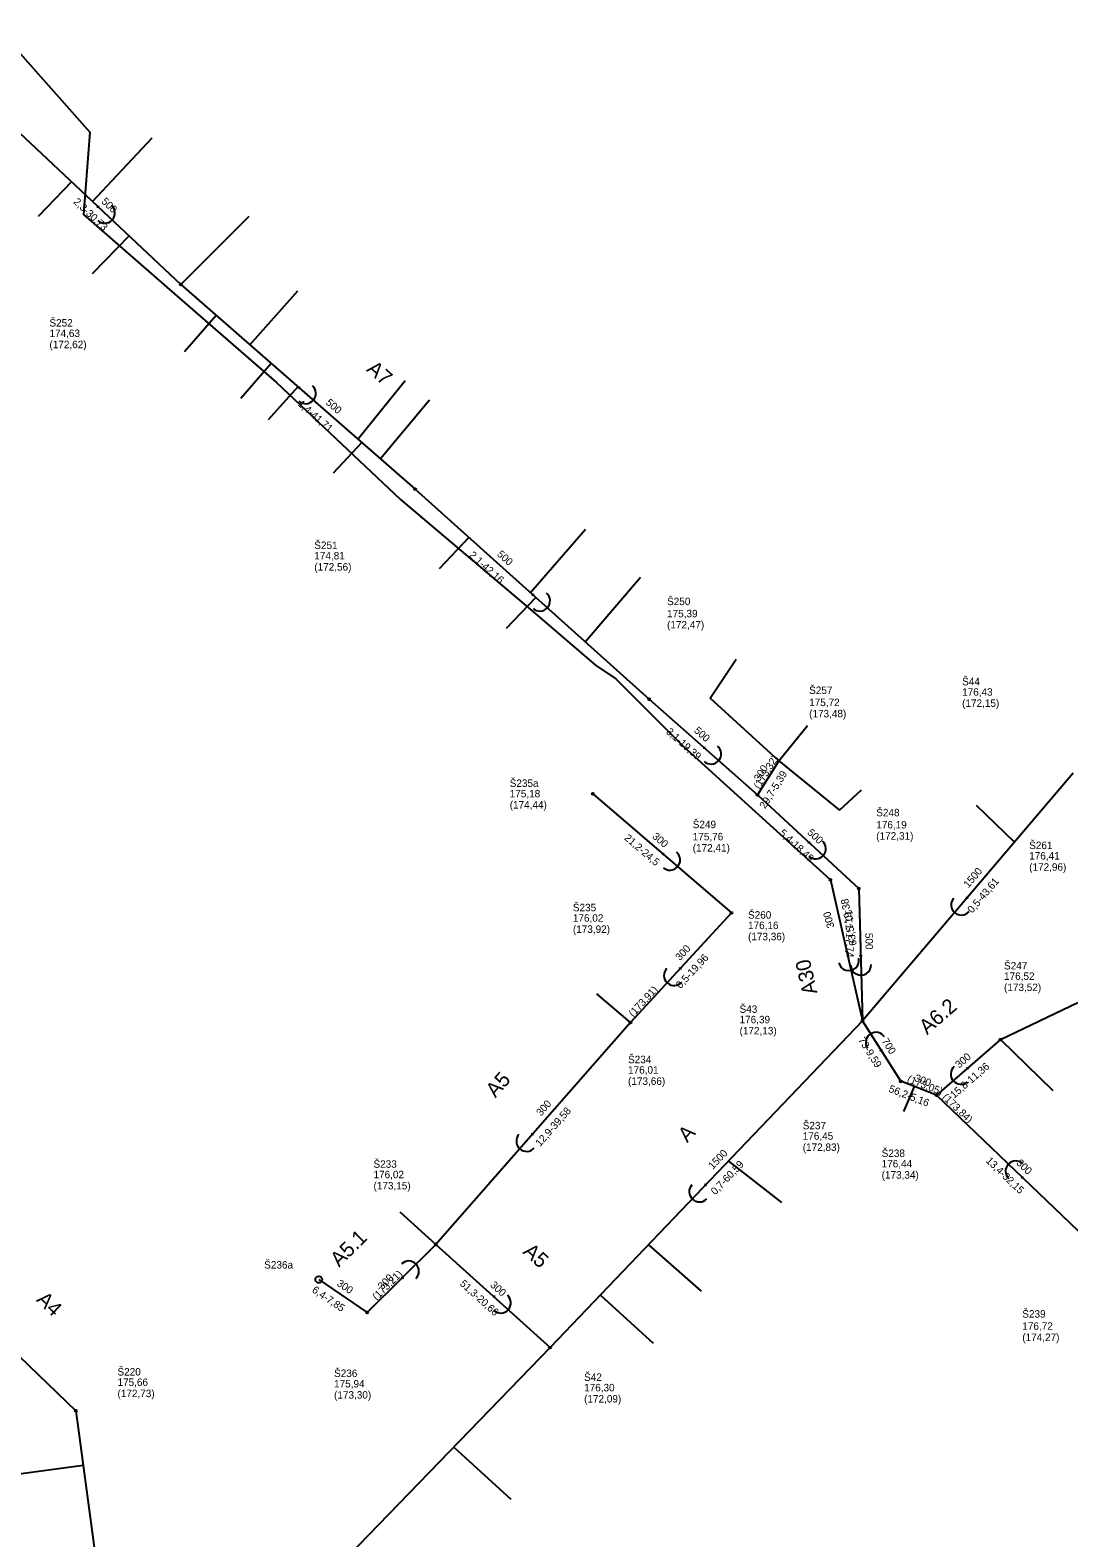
# Model space of a CAD drawing. Extents: x -548529 to -543591, y -1201432 to -1192608.
# Drawn here: x -544467.3 to -544328, y -1193048.7 to -1192846.6 of the extents above; entities that cross this region are included whole.
import ezdxf

# ---------------------------------------------------------------- set-up
doc = ezdxf.new("R2010")
doc.units = 0
for name, color, linetype in [('C3D_Bod-Značky', 7, 'Continuous'), ('C3D_Koridor', 7, 'Continuous'), ('C3D_Křižovatka', 7, 'Continuous'), ('C3D_Netisknutelná', 7, 'Continuous'), ('C3D_PP-zobrazeni v PR', 7, 'Continuous'), ('C3D_PR-Popisek', 7, 'Continuous'), ('C3D_SPR-Popisek', 7, 'Continuous'), ('C3D_Tlakove_potrubi_Popis', 7, 'Continuous'), ('C3D_ZPR-Formaty', 7, 'Continuous')]:
    doc.layers.add(name, color=color, linetype=linetype)

# ---------------------------------------------------------------- blocks, each defined once
blk = doc.blocks.new('100')
at = {"layer": 'Defpoints'}
blk.add_circle((0, 0), 0.127, dxfattribs=at)
blk = doc.blocks.new('101')
at = {"layer": 'Defpoints'}
blk.add_circle((0, 0), 0.463, dxfattribs=at)
blk = doc.blocks.new('86')
at = {"layer": 'Defpoints'}
blk.add_lwpolyline([(0.08, 0.14), (0.19, 0), (0.08, -0.14)], dxfattribs=at)
blk.add_arc((1.37, 0), 1.37, 270, 90, dxfattribs=at)
blk = doc.blocks.new('91')
at = {"layer": 'Defpoints'}
blk.add_lwpolyline([(0.08, 0.14), (0.19, 0), (0.08, -0.14)], dxfattribs=at)
blk.add_arc((1.37, 0), 1.37, 270, 90, dxfattribs=at)

msp = doc.modelspace()

# ---------------------------------------------------------------- linework, layer by layer
at = {"layer": 'C3D_Bod-Značky'}
for points in [[(-544471.435, -1192846.604), (-544459.262, -1192860.285), (-544460.127, -1192871.314), (-544447.171, -1192882.587), (-544434.216, -1192893.86), (-544417.602, -1192909.539), (-544399.58, -1192924.754), (-544391.46, -1192931.747), (-544388.746, -1192933.552), (-544379.638, -1192942.643), (-544359.967, -1192960.53)], [(-544469.46, -1192859.66), (-544447.07, -1192880.71)], [(-544447.07, -1192880.71), (-544415.63, -1192908.12)], [(-544415.63, -1192908.12), (-544384.28, -1192936.31)], [(-544384.28, -1192936.31), (-544369.74, -1192949.14)], [(-544366.86, -1192944.58), (-544369.74, -1192949.14)], [(-544327.39, -1192946.221), (-544355.66, -1192979.427)], [(-544391.799, -1192948.977), (-544373.23, -1192964.96)], [(-544369.74, -1192949.14), (-544356.16, -1192961.69)], [(-544359.967, -1192960.53), (-544355.66, -1192979.427)], [(-544356.16, -1192961.69), (-544355.66, -1192979.427)], [(-544373.23, -1192964.96), (-544386.75, -1192979.65)], [(-544386.75, -1192979.65), (-544412.86, -1193009.39)], [(-544355.66, -1192979.427), (-544397.523, -1193023.229)], [(-544350.53, -1192987.53), (-544355.66, -1192979.427)], [(-544337.14, -1192981.94), (-544345.72, -1192989.39)], [(-544345.72, -1192989.39), (-544350.53, -1192987.53)], [(-544322.5, -1193011.63), (-544345.72, -1192989.39)], [(-544494.08, -1192999.977), (-544461.138, -1193031.699)], [(-544422.07, -1193018.52), (-544412.86, -1193009.39)], [(-544412.86, -1193009.39), (-544397.523, -1193023.229)], [(-544428.557, -1193014.1), (-544422.07, -1193018.52)], [(-544397.523, -1193023.229), (-544454.373, -1193081.919)], [(-544461.138, -1193031.699), (-544454.373, -1193081.919)]]:
    msp.add_lwpolyline(points, dxfattribs=at)
at = {"layer": 'C3D_Koridor'}
for points in [[(-544458.902, -1192869.586), (-544450.905, -1192861.027)], [(-544461.721, -1192866.936), (-544466.181, -1192871.572)], [(-544447.07, -1192880.71), (-544437.895, -1192871.53)], [(-544453.994, -1192874.2), (-544458.928, -1192879.253)], [(-544437.785, -1192888.805), (-544431.359, -1192881.545)], [(-544442.299, -1192884.87), (-544446.55, -1192889.71)], [(-544434.942, -1192891.284), (-544439.012, -1192896.004)], [(-544423.318, -1192901.418), (-544416.994, -1192893.554)], [(-544431.35, -1192894.415), (-544435.346, -1192898.828)], [(-544420.297, -1192904.052), (-544413.709, -1192896.161)], [(-544422.77, -1192901.896), (-544426.618, -1192905.99)], [(-544400.182, -1192921.974), (-544392.805, -1192913.485)], [(-544408.421, -1192914.602), (-544412.403, -1192918.82)], [(-544392.835, -1192928.617), (-544385.415, -1192919.931)], [(-544399.45, -1192922.669), (-544403.425, -1192926.815)], [(-544376.1, -1192936.16), (-544372.6, -1192930.915)], [(-544366.86, -1192944.58), (-544376.1, -1192936.16)], [(-544366.86, -1192944.58), (-544363.049, -1192939.835)], [(-544366.86, -1192944.58), (-544358.74, -1192951.18)], [(-544358.74, -1192951.18), (-544355.805, -1192948.43)], [(-544335.26, -1192955.466), (-544340.377, -1192950.531)], [(-544386.75, -1192979.65), (-544391.256, -1192975.813)], [(-544337.14, -1192981.94), (-544326.769, -1192976.978)], [(-544337.14, -1192981.94), (-544330.121, -1192988.738)], [(-544348.744, -1192988.221), (-544350.169, -1192991.567)], [(-544373.617, -1192998.216), (-544366.499, -1193003.785)], [(-544412.86, -1193009.39), (-544417.626, -1193005.091)], [(-544384.347, -1193009.443), (-544377.293, -1193015.657)], [(-544390.801, -1193016.196), (-544383.712, -1193022.645)], [(-544410.471, -1193036.596), (-544402.796, -1193043.551)], [(-544460.152, -1193039.016), (-544482.684, -1193042.051)]]:
    msp.add_lwpolyline(points, dxfattribs=at)

# ---------------------------------------------------------------- block references
at = {"layer": 'C3D_PP-zobrazeni v PR'}
for name, p, xscale, yscale, rotation in [('100', (-544447.07, -1192880.71), 1.0000000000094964, 1.0000000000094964, 137.9999986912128), ('100', (-544415.63, -1192908.12), 1.0000000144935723, 1.0000000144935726, 139.00000089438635), ('100', (-544384.28, -1192936.31), 1.0000000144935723, 1.0000000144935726, 139.00000089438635), ('100', (-544366.86, -1192944.58), 0.9999999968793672, 0.9999999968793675, -122.00000027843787), ('100', (-544391.799, -1192948.977), 1.0000000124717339, 1.0000000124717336, -40.00000131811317), ('100', (-544369.74, -1192949.14), 1.0000000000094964, 1.0000000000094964, 137.9999986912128), ('100', (-544359.967, -1192960.53), 1.0000000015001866, 1.0000000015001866, 120.99999982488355), ('100', (-544356.16, -1192961.69), 1.000000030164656, 1.000000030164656, 114.99999971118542), ('100', (-544373.23, -1192964.96), 1.0000000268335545, 1.0000000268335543, -86.00000028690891), ('100', (-544386.75, -1192979.65), 1.0000000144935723, 1.0000000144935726, -130.99999910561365), ('100', (-544355.66, -1192979.427), 1.0000000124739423, 1.000000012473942, 112.99999954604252), ('100', (-544337.14, -1192981.94), 1.0000000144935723, 1.0000000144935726, -139.00000089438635), ('100', (-544350.53, -1192987.53), 1.000000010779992, 1.0000000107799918, 141.00000108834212), ('100', (-544345.72, -1192989.39), 1.000000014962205, 1.0000000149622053, 89.0000000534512), ('100', (-544412.86, -1193009.39), 1.0000000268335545, 1.0000000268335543, 93.99999971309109), ('101', (-544428.557, -1193014.1), 0.9999999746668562, 0.999999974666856, 145.99999954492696), ('100', (-544422.07, -1193018.52), 1.0011217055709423, 1.0011217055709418, -173.41739016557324), ('100', (-544397.523, -1193023.229), 1.00000000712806, 1.00000000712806, -133.00000056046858), ('100', (-544461.138, -1193031.699), 0.9999999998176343, 0.9999999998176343, 116.9999993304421)]:
    msp.add_blockref(name, p, dxfattribs=dict(at, xscale=xscale, yscale=yscale, rotation=rotation))
at = {"layer": 'C3D_SPR-Popisek'}
for name, p, xscale, yscale, rotation in [('91', (-544458.265, -1192870.185), 1.00000000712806, 1.00000000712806, -43.0000005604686), ('91', (-544431.35, -1192894.415), 1.0000000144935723, 1.0000000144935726, -40.99999910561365), ('91', (-544399.955, -1192922.215), 1.0000000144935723, 1.0000000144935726, -40.99999910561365), ('91', (-544377.01, -1192942.725), 1.0000000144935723, 1.0000000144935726, -40.99999910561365), ('91', (-544362.95, -1192955.415), 1.0000000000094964, 1.0000000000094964, -42.000001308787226), ('91', (-544382.514, -1192956.968), 1.0000000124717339, 1.0000000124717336, -40.00000131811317), ('91', (-544341.525, -1192962.824), 1.0000000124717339, 1.0000000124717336, -130.0000013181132), ('86', (-544357.813, -1192969.978), 0.9999999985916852, 0.9999999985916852, -76.99999972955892), ('91', (-544355.91, -1192970.558), 1.00000001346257, 1.0000000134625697, -88.00000009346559), ('91', (-544379.99, -1192972.305), 1.0000000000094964, 1.0000000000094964, -132.0000013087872), ('91', (-544353.095, -1192983.478), 0.9999999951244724, 0.9999999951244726, 123.00000127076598), ('91', (-544341.43, -1192985.665), 1.0000000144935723, 1.0000000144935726, -139.00000089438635), ('91', (-544399.805, -1192994.52), 1.0000000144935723, 1.0000000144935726, -130.99999910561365), ('91', (-544334.11, -1193000.51), 1.00000000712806, 1.00000000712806, 136.99999943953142), ('91', (-544376.592, -1193001.328), 1.00000000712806, 1.00000000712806, -133.00000056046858), ('91', (-544417.465, -1193013.955), 0.999999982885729, 0.9999999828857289, 45), ('91', (-544405.192, -1193016.31), 1.0000000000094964, 1.0000000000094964, -42.000001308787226)]:
    msp.add_blockref(name, p, dxfattribs=dict(at, xscale=xscale, yscale=yscale, rotation=rotation))

# ---------------------------------------------------------------- texts
at = {"layer": 'C3D_Křižovatka'}
for s, p in [('Š252', (-544464.67, -1192886.34)), ('Š251', (-544429.16, -1192916.16)), ('Š250', (-544381.86, -1192923.69)), ('Š257', (-544362.81, -1192935.6)), ('Š44', (-544342.3, -1192934.431)), ('Š235a', (-544402.959, -1192948.057)), ('Š248', (-544353.81, -1192952)), ('Š249', (-544378.42, -1192953.59)), ('Š261', (-544333.308, -1192956.394)), ('Š235', (-544394.49, -1192964.73)), ('Š260', (-544371.007, -1192965.72)), ('Š247', (-544336.68, -1192972.53)), ('Š43', (-544372.14, -1192978.347)), ('Š234', (-544387.09, -1192985.1)), ('Š237', (-544363.67, -1192993.96)), ('Š238', (-544353.09, -1192997.67)), ('Š233', (-544421.22, -1192999.12)), ('Š236a', (-544435.877, -1193012.63)), ('Š239', (-544334.23, -1193019.21)), ('Š220', (-544455.548, -1193026.969)), ('Š236', (-544426.51, -1193027.17)), ('Š42', (-544392.983, -1193027.689))]:
    msp.add_text(s, height=1, dxfattribs=at).set_placement(p)
at = {"layer": 'C3D_Netisknutelná'}
for s, rotation, p in [('A7', 318.92, (-544422.27, -1192892.228)), ('A30', 102.81, (-544361.694, -1192975.662)), ('A6.2', 40.97, (-544346.992, -1192981.356)), ('A5', 48.72, (-544404.873, -1192989.838)), ('A', 46.3, (-544379.164, -1192995.827)), ('A5.1', 44.75, (-544425.833, -1193012.526)), ('A5', 317.94, (-544401.303, -1193010.524)), ('A4', 316.08, (-544466.527, -1193016.931))]:
    msp.add_text(s, height=2, rotation=rotation, dxfattribs=at).set_placement(p)
at = {"layer": 'C3D_PR-Popisek'}
for s, rotation, p in [('500', 316.77, (-544457.789, -1192869.679)), ('500', 318.92, (-544427.703, -1192896.661)), ('500', 318.04, (-544404.738, -1192916.979)), ('500', 318.58, (-544378.329, -1192940.634)), ('300', 57.72, (-544369.468, -1192947.4)), ('300', 319.28, (-544383.926, -1192954.826)), ('500', 317.26, (-544363.141, -1192954.282)), ('1500', 49.59, (-544341.457, -1192961.67)), ('300', 105.81, (-544359.4, -1192966.834)), ('500', 271.61, (-544355.292, -1192967.642)), ('300', 47.37, (-544380.142, -1192971.434)), ('700', 302.34, (-544353.126, -1192982.122)), ('300', 40.97, (-544342.703, -1192985.84)), ('300', 338.86, (-544348.775, -1192987.455)), ('300', 48.72, (-544398.76, -1192992.264)), ('1500', 46.3, (-544375.716, -1192999.396)), ('300', 316.23, (-544335.114, -1192998.577)), ('300', 44.75, (-544420.056, -1193015.534)), ('300', 325.73, (-544426.237, -1193014.839)), ('300', 317.94, (-544405.653, -1193014.955))]:
    msp.add_text(s, height=1, rotation=rotation, dxfattribs=at).set_placement(p)
at = {"layer": 'C3D_Tlakove_potrubi_Popis'}
for s, p in [('(172,62)', (-544464.67, -1192889.24)), ('174,63 ', (-544464.67, -1192887.74)), ('174,81 ', (-544429.16, -1192917.56)), ('(172,56)', (-544429.16, -1192919.06)), ('175,39 ', (-544381.86, -1192925.32)), ('(172,47)', (-544381.86, -1192926.82)), ('175,72 ', (-544362.81, -1192937.23)), ('(172,15)', (-544342.3, -1192937.331)), ('176,43 ', (-544342.3, -1192935.831)), ('(173,48)', (-544362.81, -1192938.73)), ('175,18 ', (-544402.959, -1192949.457)), ('(174,44)', (-544402.959, -1192950.957)), ('176,19 ', (-544353.81, -1192953.63)), ('175,76 ', (-544378.42, -1192955.22)), ('(172,31)', (-544353.81, -1192955.13)), ('(172,41)', (-544378.42, -1192956.72)), ('176,41 ', (-544333.308, -1192957.794)), ('(172,96)', (-544333.308, -1192959.294)), ('(173,92)', (-544394.49, -1192967.63)), ('176,02 ', (-544394.49, -1192966.13)), ('176,16 ', (-544371.007, -1192967.12)), ('(173,36)', (-544371.007, -1192968.62)), ('176,52 ', (-544336.68, -1192973.93)), ('(173,52)', (-544336.68, -1192975.43)), ('176,39 ', (-544372.14, -1192979.747)), ('(172,13)', (-544372.14, -1192981.247)), ('(173,66)', (-544387.09, -1192988)), ('176,01 ', (-544387.09, -1192986.5)), ('176,45 ', (-544363.67, -1192995.36)), ('(172,83)', (-544363.67, -1192996.86)), ('176,44 ', (-544353.09, -1192999.07)), ('(173,15)', (-544421.22, -1193002.02)), ('176,02 ', (-544421.22, -1193000.52)), ('(173,34)', (-544353.09, -1193000.57)), ('(174,27)', (-544334.23, -1193022.34)), ('176,72 ', (-544334.23, -1193020.84)), ('175,66 ', (-544455.548, -1193028.369)), ('175,94 ', (-544426.51, -1193028.57)), ('(172,73)', (-544455.548, -1193029.869)), ('(173,30)', (-544426.51, -1193030.07)), ('(172,09)', (-544392.983, -1193030.589)), ('176,30 ', (-544392.983, -1193029.089))]:
    msp.add_text(s, height=1, dxfattribs=at).set_placement(p)
at = {"layer": 'C3D_ZPR-Formaty'}
for s, rotation, p in [('2,3-30,73', 316.77, (-544461.535, -1192869.719)), ('1,4-41,71', 318.92, (-544431.448, -1192896.852)), ('2,1-42,16', 318.04, (-544408.482, -1192917.104)), ('3,1-19,39', 318.58, (-544382.07, -1192940.787)), ('  (173,32)   ', 57.72, (-544369.909, -1192949.033)), ('29,7-5,39', 57.72, (-544368.716, -1192951.07)), ('21,2-24,5', 319.28, (-544387.675, -1192955.035)), ('5,4-18,49', 317.26, (-544366.894, -1192954.358)), ('0,5-43,61', 49.59, (-544340.94, -1192965.061)), ('63,5-19,38', 100.68, (-544356.409, -1192969.25)), ('10,1-17,74', 271.61, (-544357.98, -1192964.562)), ('0,5-19,96', 47.37, (-544380.051, -1192975.178)), ('  (173,91)   ', 47.37, (-544386.897, -1192979.515)), ('73-9,59', 302.34, (-544356.282, -1192981.991)), ('15,8-11,36', 40.97, (-544343.374, -1192989.873)), ('  (173,05)   ', 338.86, (-544350.458, -1192987.343)), ('56,2-5,16', 338.86, (-544352.228, -1192988.907)), ('  (173,84)   ', 316.23, (-544345.582, -1192989.246)), ('12,9-39,58', 48.72, (-544398.876, -1192996.344)), ('0,7-60,59', 46.3, (-544375.389, -1193002.82)), ('13,4-32,15', 316.23, (-544339.187, -1192998.279)), ('  (173,21)   ', 44.75, (-544421.31, -1193017.485)), ('6,4-7,85', 325.73, (-544429.555, -1193015.719)), ('51,3-20,66', 317.94, (-544409.73, -1193014.774))]:
    msp.add_text(s, height=1, rotation=rotation, dxfattribs=at).set_placement(p)

doc.saveas('drawing.dxf')
